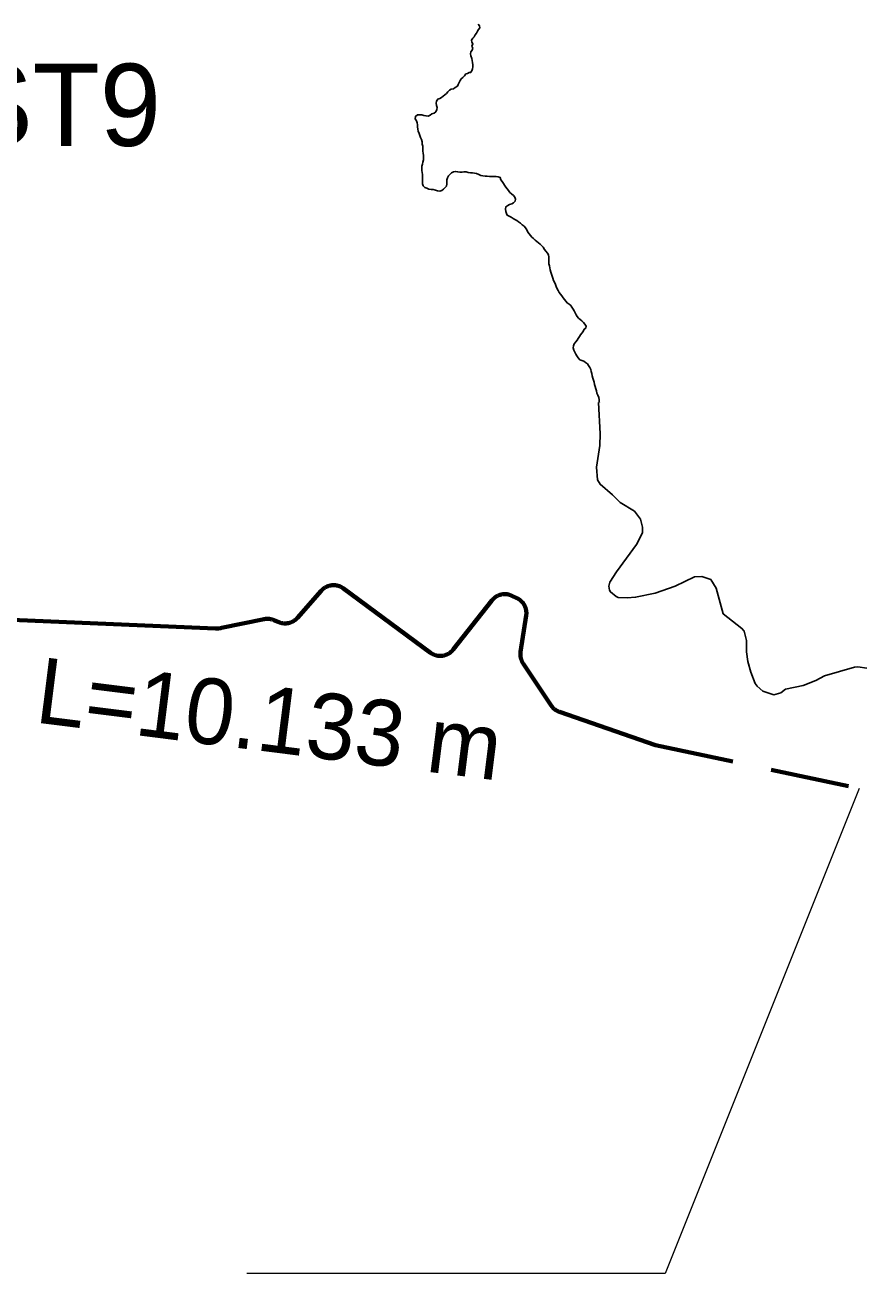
# Model space of a CAD drawing. Extents: x -1643653 to 4543381, y 1624270 to 13878484.
# Drawn here: x 731441 to 736555, y 8953037 to 8960656 of the extents above; entities that cross this region are included whole.
import ezdxf
from ezdxf.enums import TextEntityAlignment as Align

# ---------------------------------------------------------------- set-up
doc = ezdxf.new("R2010")
doc.units = 0
doc.header["$LTSCALE"] = 160
doc.linetypes.add('MEDIUM_DASHED', pattern=[4.5, 3, -1.5])
for name, color, linetype, lineweight in [('24', 7, 'Continuous', 25), ('50', 7, 'Continuous', 13), ('54', 7, 'Continuous', 25), ('60', 7, 'Continuous', 13), ('61', 7, 'Continuous', 70)]:
    doc.layers.add(name, color=color, linetype=linetype, lineweight=lineweight)

msp = doc.modelspace()

# ---------------------------------------------------------------- linework, layer by layer
at = {"layer": '24'}
for points in [[(734197.1, 8960661.3), (734205.7, 8960651.9), (734207.8, 8960639.2), (734198.6, 8960629.6), (734192.4, 8960618.6), (734185.6, 8960607.7), (734178.1, 8960596.2), (734172.6, 8960584.9), (734163.4, 8960576.4), (734155.8, 8960565.4), (734158.7, 8960553), (734164.3, 8960541.4), (734158.6, 8960528.3), (734163.7, 8960516.2), (734160.8, 8960503.2), (734153, 8960493), (734150.5, 8960481.4), (734151.3, 8960469.9), (734157.4, 8960454), (734161.1, 8960441.5), (734162.3, 8960428.1), (734164.3, 8960415.1), (734164.5, 8960402.2), (734163.1, 8960389.5), (734158.2, 8960377.6), (734150.7, 8960367.4), (734141.7, 8960366.9), (734131.8, 8960362.7), (734121.8, 8960358.9), (734113.8, 8960347.7), (734103.8, 8960338.3), (734094.2, 8960329.3), (734087.1, 8960318.7), (734080.9, 8960307.4), (734075.3, 8960295.5), (734070.1, 8960283.9), (734057.8, 8960277.4), (734046.2, 8960267.9), (734033.3, 8960266.2), (734022.6, 8960259.8), (734013.1, 8960249.4), (734003.4, 8960241), (733993.2, 8960233), (733983.7, 8960224.1), (733973.5, 8960216.7), (733963.2, 8960208.9), (733950.5, 8960205.4), (733944.1, 8960193.5), (733941.6, 8960180.5), (733944.1, 8960167.2), (733947, 8960154.9), (733945.1, 8960142.1), (733938.6, 8960128.8), (733928.6, 8960120.9), (733915.5, 8960116.3), (733904.7, 8960108.7), (733893.3, 8960102.3), (733880.1, 8960103.4), (733866.8, 8960106.6), (733854.8, 8960111), (733841.7, 8960111.4), (733828.3, 8960110), (733814.9, 8960100.8), (733814.5, 8960086.4)], [(733814.5, 8960086.4), (733821.2, 8960074.7), (733825.6, 8960062.8), (733828.5, 8960050.2), (733828.2, 8960037.1), (733829.8, 8960023.7), (733832, 8960011.3), (733837.2, 8959997.6), (733842.3, 8959985.5), (733846.4, 8959973.3), (733851.2, 8959961.1), (733856.7, 8959946), (733856.5, 8959932.7), (733859.7, 8959919.4), (733860.2, 8959902.9), (733860.7, 8959889.6), (733862.5, 8959876.9), (733863.4, 8959864), (733863.7, 8959849.9), (733863.4, 8959837), (733861.1, 8959823.5), (733857.2, 8959810.9), (733854.1, 8959798.5), (733853.8, 8959785.2), (733855, 8959772.4), (733857, 8959759.4), (733858.9, 8959746.8), (733859, 8959733.6), (733858.7, 8959720.9), (733857.8, 8959703.4), (733857.6, 8959690.8), (733863, 8959679), (733871.7, 8959669.4), (733885.4, 8959664.8), (733896.9, 8959659), (733910.2, 8959656.5), (733923.4, 8959656), (733936.8, 8959652.6), (733949.7, 8959648), (733962.9, 8959647.2), (733975.6, 8959651.2), (733986.2, 8959658), (733994.9, 8959667), (734003.2, 8959676.8), (734005.4, 8959690), (734005.2, 8959702.8), (734006, 8959715.4), (734010.5, 8959727.8), (734016, 8959739.1), (734025.6, 8959748.8), (734034.4, 8959758.2), (734046.6, 8959764.4), (734059.1, 8959766.7), (734072.5, 8959763.4), (734085.2, 8959761.1), (734098.3, 8959761.5), (734111, 8959764.2), (734124.5, 8959764.4), (734136.4, 8959760.3), (734149.3, 8959757.9), (734162.2, 8959757), (734174.9, 8959755.6), (734187.2, 8959752.9), (734200.8, 8959747), (734212.5, 8959740.7), (734225.9, 8959738.8), (734238.5, 8959737.8), (734251.4, 8959736.5), (734265.3, 8959735.4), (734278, 8959735.1), (734291.5, 8959734.8), (734305.5, 8959734.6), (734319, 8959734.3), (734331.1, 8959729), (734335, 8959715.4), (734342.8, 8959704.5), (734350, 8959693), (734357.1, 8959681.8), (734365.1, 8959671.5), (734373.2, 8959659.9), (734381.5, 8959649.9), (734389.5, 8959638.6), (734399.3, 8959630), (734410.7, 8959620.2), (734420.1, 8959610.5), (734423.1, 8959597.8), (734421.3, 8959585.3), (734412.2, 8959574.8), (734400.8, 8959568.8), (734388.1, 8959565.2), (734377, 8959559.1), (734365.5, 8959551.4), (734363.3, 8959537.6), (734364.5, 8959523.6), (734368.1, 8959511.4), (734373.9, 8959500.1), (734384.8, 8959493.7), (734396.7, 8959487.8), (734408.5, 8959481), (734420.4, 8959474), (734431.6, 8959467.6)], [(734431.6, 8959467.6), (734442.2, 8959459.5), (734454.6, 8959451), (734464.8, 8959442.5), (734475.5, 8959433.5), (734485.1, 8959423.8), (734492, 8959411.7), (734498.5, 8959397.6), (734506.2, 8959386.8), (734514.6, 8959376.3), (734523.2, 8959366.7), (734533.2, 8959357.8), (734543.6, 8959348.3), (734552.9, 8959339.8), (734563.9, 8959331.8), (734574, 8959323.8), (734582.8, 8959314.8), (734592.3, 8959305), (734600.5, 8959291.5), (734608, 8959280.9), (734617.5, 8959269.6), (734624.7, 8959258.8), (734626.1, 8959245.7), (734626, 8959232.8), (734625.7, 8959218), (734626.1, 8959205.1), (734630.5, 8959193), (734632.5, 8959180.1), (734634.7, 8959167), (734637.9, 8959154.3), (734643.1, 8959141.8), (734646.8, 8959129.1), (734650.6, 8959116.5), (734655, 8959103.9), (734660.9, 8959092.6), (734667.1, 8959078.1), (734671.8, 8959066.3), (734676.4, 8959053.3), (734682.5, 8959041.6), (734688.8, 8959030.1), (734696.8, 8959019.8), (734705.8, 8959008.9), (734713.8, 8958998), (734721.6, 8958987.3), (734729.5, 8958976.4), (734737.8, 8958967), (734749.1, 8958959.3), (734759.3, 8958951.2), (734767.1, 8958940.8), (734774, 8958929.3), (734779.5, 8958917.7), (734786.1, 8958906.2), (734792.6, 8958894.8), (734799.4, 8958883.8), (734806.8, 8958873.7), (734816.8, 8958866), (734827.6, 8958858), (734837.4, 8958847.7), (734845.6, 8958838), (734853, 8958826), (734851.7, 8958813.5), (734841, 8958806.3), (734834.3, 8958793.6), (734826.8, 8958783.2), (734819.6, 8958772.8), (734812.1, 8958761.7), (734805.2, 8958751.1), (734799.5, 8958740), (734791.5, 8958729.7), (734781.1, 8958717.5), (734775.6, 8958705.8), (734774.8, 8958692.8), (734778.6, 8958679.1), (734783.7, 8958666.9), (734789.7, 8958655.6), (734797.2, 8958644.2), (734804.6, 8958632.4), (734815.2, 8958620.2), (734827.2, 8958615.9), (734839.7, 8958611.5), (734850.3, 8958604.2), (734860.7, 8958595.4), (734868.5, 8958585.5), (734875.6, 8958573.9), (734881.5, 8958562.3), (734884.5, 8958549.8), (734887.6, 8958536.7), (734889.9, 8958522.8), (734894.7, 8958509.9), (734898.2, 8958497.2), (734901.8, 8958484), (734905, 8958471.2), (734908.4, 8958459.1), (734912.4, 8958444.8), (734915.5, 8958432.2), (734918.6, 8958417.7), (734924.1, 8958405.6), (734930.5, 8958390.5), (734931.8, 8958377.5), (734933, 8958364.6), (734934.6, 8958360.2)], [(734927.5, 8958360.3), (734939, 8958171.4), (734935.7, 8958098.7), (734916.8, 8957966.9), (734921.7, 8957891.6), (734939, 8957863.7), (735013.5, 8957800), (735061, 8957752), (735146.6, 8957699.9), (735184.6, 8957651.3), (735196.8, 8957602.3), (735195.5, 8957569.3), (735158.9, 8957496.6), (735038.3, 8957331.8), (734996.3, 8957267.8), (734991.1, 8957244.5), (734995.8, 8957220.6), (735001.9, 8957208.7), (735035.1, 8957182), (735048.9, 8957175.4), (735102, 8957172.8), (735153.5, 8957176.6), (735272.3, 8957201.5), (735395, 8957245), (735511.8, 8957301.6), (735556.6, 8957302.6), (735610.7, 8957285.4), (735644.8, 8957232.6), (735686.2, 8957076.6), (735800.6, 8956987.3), (735813.5, 8956971.2), (735828, 8956914.6), (735827.4, 8956845.1), (735835.8, 8956785.5), (735854.7, 8956721.8), (735881.3, 8956651.3), (735892.6, 8956636), (735928.3, 8956605.5), (735994.1, 8956583.9), (736036.3, 8956595.8), (736065.4, 8956618.2), (736173.8, 8956640.7), (736249.4, 8956670.3), (736303.6, 8956698.2), (736484.3, 8956752.4), (736504.6, 8956754.1), (736560.1, 8956744.7)]]:
    msp.add_lwpolyline(points, dxfattribs=at)
at = {"layer": '50'}
msp.add_lwpolyline([(736512.8, 8956014.4), (735332.8, 8953064.6), (732790.7, 8953064.6)], dxfattribs=at)
at = {"layer": '60', "lineweight": 25}
msp.add_spline([(814781, 9009175.5), (814787.2, 9009173.4), (814796.9, 9009173.4), (814799.4, 9009172.4), (814805.1, 9009174.5), (814805.6, 9009176.5), (814811.7, 9009179.5), (814811.7, 9009179.5), (814801.5, 9009181), (814790.7, 9009181.5), (814784.1, 9009183.1), (814777.4, 9009185.1), (814778.4, 9009175.5)], degree=3, dxfattribs=at)
at = {"layer": '61', "linetype": 'MEDIUM_DASHED'}
msp.add_line((735275.1, 8956278.2), (737750.5, 8955750.6), dxfattribs=at)
at = {"layer": '61'}
for points in [[(733310.4, 8957250.1), (733307.6, 8957249.9), (733304.8, 8957249.6), (733302, 8957249.2), (733299.2, 8957248.7), (733296.5, 8957248.1), (733293.7, 8957247.5), (733291, 8957246.8), (733288.2, 8957246), (733285.6, 8957245.1), (733282.9, 8957244.2), (733280.2, 8957243.2), (733277.6, 8957242.1), (733275.1, 8957240.9), (733272.5, 8957239.7), (733270, 8957238.3), (733267.5, 8957237), (733265.1, 8957235.5), (733262.7, 8957234), (733260.4, 8957232.4), (733258.1, 8957230.8), (733255.8, 8957229.1), (733253.6, 8957227.3), (733251.5, 8957225.5), (733249.4, 8957223.6), (733247.3, 8957221.6), (733245.4, 8957219.6), (733243.4, 8957217.5), (733242.4, 8957216.3), (733097.8, 8957051.6), (733095.9, 8957049.5), (733094, 8957047.5), (733092, 8957045.5), (733089.9, 8957043.5), (733087.8, 8957041.7), (733085.6, 8957039.8), (733083.4, 8957038.1), (733081.1, 8957036.4), (733078.8, 8957034.8), (733076.4, 8957033.2), (733074, 8957031.8), (733071.6, 8957030.3), (733069.1, 8957029), (733066.6, 8957027.7), (733064, 8957026.5), (733061.4, 8957025.4), (733058.8, 8957024.3), (733056.1, 8957023.3), (733053.5, 8957022.4), (733050.8, 8957021.6), (733048, 8957020.8), (733045.3, 8957020.1), (733042.5, 8957019.5), (733039.7, 8957019), (733036.9, 8957018.6), (733034.1, 8957018.2), (733031.3, 8957017.9), (733028.5, 8957017.7), (733025.7, 8957017.6), (733022.8, 8957017.6), (733020, 8957017.6), (733017.2, 8957017.7), (733014.4, 8957017.9), (733011.6, 8957018.2), (733008.8, 8957018.5), (733006, 8957019), (733003.2, 8957019.5), (733000.4, 8957020.1), (732997.7, 8957020.7), (732994.9, 8957021.5), (732992.2, 8957022.3), (732989.5, 8957023.2), (732986.9, 8957024.2), (732984.3, 8957025.2), (732983.7, 8957025.4), (732954.4, 8957037.8), (732951.8, 8957038.9), (732949.2, 8957039.9), (732946.5, 8957040.8), (732943.8, 8957041.6), (732941, 8957042.4), (732938.3, 8957043.1), (732935.5, 8957043.7), (732932.8, 8957044.2), (732930, 8957044.7), (732927.2, 8957045), (732924.3, 8957045.3), (732921.5, 8957045.5), (732918.7, 8957045.7), (732915.9, 8957045.7), (732913.1, 8957045.7), (732910.2, 8957045.6), (732907.4, 8957045.4), (732904.6, 8957045.1), (732901.8, 8957044.8), (732899, 8957044.3), (732896.2, 8957043.8), (732895.1, 8957043.6), (732636.3, 8956989.8), (732632.9, 8956989.1), (732629.5, 8956988.5)], [(734319.3, 8957187.8), (734316.8, 8957186.6), (734314.2, 8957185.4), (734311.7, 8957184.1), (734309.2, 8957182.7), (734306.8, 8957181.3), (734304.4, 8957179.8), (734302, 8957178.2), (734299.7, 8957176.6), (734297.5, 8957174.9), (734295.2, 8957173.1), (734293.1, 8957171.3), (734291, 8957169.4), (734288.9, 8957167.5), (734286.9, 8957165.5), (734285, 8957163.4), (734283.1, 8957161.3), (734281.3, 8957159.1), (734280, 8957157.6), (734044.6, 8956858.3), (734042.8, 8956856.1), (734041, 8956853.9), (734039.1, 8956851.8), (734037.1, 8956849.8), (734035.1, 8956847.8), (734033, 8956845.9), (734030.9, 8956844), (734028.7, 8956842.2), (734026.5, 8956840.5), (734024.2, 8956838.8), (734021.9, 8956837.2), (734019.5, 8956835.6), (734017.1, 8956834.1), (734014.7, 8956832.7), (734012.2, 8956831.4), (734009.6, 8956830.1), (734007.1, 8956828.9), (734004.5, 8956827.8), (734001.9, 8956826.7), (733999.2, 8956825.8), (733996.5, 8956824.9), (733993.8, 8956824), (733991.1, 8956823.3), (733988.3, 8956822.6), (733985.6, 8956822), (733982.8, 8956821.5), (733980, 8956821.1), (733977.2, 8956820.7), (733974.4, 8956820.4), (733971.6, 8956820.2), (733968.7, 8956820.1), (733965.9, 8956820.1), (733963.1, 8956820.1), (733960.2, 8956820.2), (733957.4, 8956820.5), (733954.6, 8956820.7), (733951.8, 8956821.1), (733949, 8956821.5), (733946.2, 8956822.1), (733943.5, 8956822.7), (733940.7, 8956823.3), (733938, 8956824.1), (733935.3, 8956824.9), (733932.6, 8956825.8), (733930, 8956826.8), (733927.3, 8956827.8), (733924.8, 8956829), (733922.2, 8956830.2), (733919.7, 8956831.5), (733917.2, 8956832.8), (733914.7, 8956834.2), (733912.3, 8956835.7), (733910, 8956837.3), (733907.6, 8956838.9), (733906.6, 8956839.6), (733376.9, 8957230.8), (733374.7, 8957232.5), (733372.3, 8957234), (733369.9, 8957235.6), (733367.5, 8957237), (733365, 8957238.4), (733362.5, 8957239.7), (733360, 8957240.9), (733357.4, 8957242.1), (733354.8, 8957243.2), (733352.1, 8957244.2), (733349.5, 8957245.1), (733346.8, 8957246), (733344.1, 8957246.8), (733341.3, 8957247.5), (733338.6, 8957248.1), (733335.8, 8957248.7), (733333, 8957249.2), (733330.2, 8957249.6), (733327.4, 8957249.9), (733324.6, 8957250.1), (733321.8, 8957250.3), (733318.9, 8957250.4), (733316.1, 8957250.4), (733313.3, 8957250.3), (733310.4, 8957250.1)], [(734463.5, 8956785.6), (734462.3, 8956788.2), (734461.2, 8956790.8), (734460.1, 8956793.4), (734459.2, 8956796.1), (734458.3, 8956798.8), (734457.5, 8956801.5), (734456.7, 8956804.2), (734456.1, 8956807), (734455.5, 8956809.7), (734455, 8956812.5), (734454.6, 8956815.3), (734454.2, 8956818.1), (734453.9, 8956820.9), (734453.7, 8956823.7), (734453.6, 8956826.6), (734453.6, 8956829.4), (734453.7, 8956832.2), (734453.8, 8956835.1), (734454, 8956837.9), (734454.3, 8956840.7), (734454.7, 8956843.5), (734454.8, 8956844.1), (734488.7, 8957065.8), (734489, 8957068.6), (734489.3, 8957071.5), (734489.6, 8957074.3), (734489.7, 8957077.1), (734489.8, 8957079.9), (734489.8, 8957082.8), (734489.7, 8957085.6), (734489.5, 8957088.4), (734489.3, 8957091.2), (734488.9, 8957094), (734488.5, 8957096.8), (734488, 8957099.6), (734487.5, 8957102.4), (734486.8, 8957105.1), (734486.1, 8957107.9), (734485.3, 8957110.6), (734484.4, 8957113.3), (734483.5, 8957115.9), (734482.5, 8957118.6), (734481.3, 8957121.2), (734480.2, 8957123.8), (734478.9, 8957126.3), (734477.6, 8957128.8), (734476.2, 8957131.2), (734474.8, 8957133.7), (734473.2, 8957136.1), (734471.7, 8957138.4), (734470, 8957140.7), (734468.3, 8957142.9), (734466.5, 8957145.1), (734464.6, 8957147.3), (734462.7, 8957149.4), (734460.8, 8957151.4), (734458.8, 8957153.4), (734456.7, 8957155.3), (734454.5, 8957157.2), (734452.4, 8957159), (734450.1, 8957160.7), (734447.8, 8957162.4), (734445.5, 8957164), (734443.2, 8957165.5), (734440.7, 8957167), (734438.3, 8957168.4), (734435.8, 8957169.7), (734433.3, 8957171), (734432.8, 8957171.2), (734401.7, 8957186.1), (734399.1, 8957187.2), (734396.5, 8957188.4), (734393.8, 8957189.4), (734391.2, 8957190.3), (734388.5, 8957191.2), (734385.8, 8957192), (734383.1, 8957192.8), (734380.3, 8957193.4), (734377.5, 8957194), (734374.8, 8957194.5), (734372, 8957194.9), (734369.2, 8957195.2), (734366.3, 8957195.5), (734363.5, 8957195.7), (734360.7, 8957195.8), (734357.8, 8957195.8), (734355, 8957195.7), (734352.2, 8957195.6), (734349.4, 8957195.4), (734346.6, 8957195.1), (734343.8, 8957194.7), (734341, 8957194.2), (734338.2, 8957193.7), (734335.4, 8957193.1), (734332.7, 8957192.4), (734330, 8957191.6), (734327.3, 8957190.8), (734324.6, 8957189.8), (734322, 8957188.8), (734319.3, 8957187.8)], [(732629.5, 8956988.5), (732626.1, 8956988), (732622.6, 8956987.6), (732619.2, 8956987.2), (732615.7, 8956987), (732612.3, 8956986.8), (732608.8, 8956986.7), (732605.3, 8956986.6), (732601.9, 8956986.7), (732599.5, 8956986.8), (731312.7, 8957040.8)], [(735275.1, 8956278.2), (734691.7, 8956479.3), (734689.1, 8956480.2), (734686.4, 8956481.3), (734683.8, 8956482.4), (734681.3, 8956483.6), (734678.7, 8956484.8), (734676.2, 8956486.1), (734673.8, 8956487.5), (734671.3, 8956489), (734669, 8956490.5), (734666.6, 8956492.1), (734664.3, 8956493.8), (734662.1, 8956495.5), (734659.9, 8956497.3), (734657.8, 8956499.2), (734655.7, 8956501.1), (734653.7, 8956503), (734651.7, 8956505.1), (734649.8, 8956507.1), (734647.9, 8956509.3), (734646.1, 8956511.5), (734644.4, 8956513.7), (734642.7, 8956516), (734641.2, 8956518.2), (734470.5, 8956773.4), (734469, 8956775.7), (734467.5, 8956778.1), (734466.1, 8956780.6), (734464.8, 8956783.1), (734463.5, 8956785.6)]]:
    msp.add_lwpolyline(points, dxfattribs=at)

# ---------------------------------------------------------------- texts
at = {"layer": '50'}
msp.add_text('L=10.133 m', height=400, rotation=352.836, dxfattribs=at).set_placement((731494.7, 8956416.4))
at = {"layer": '54'}
msp.add_text('TAST9', height=500, dxfattribs=at).set_placement((731227.8, 8959921.4), align=Align.CENTER)

doc.saveas('drawing.dxf')
